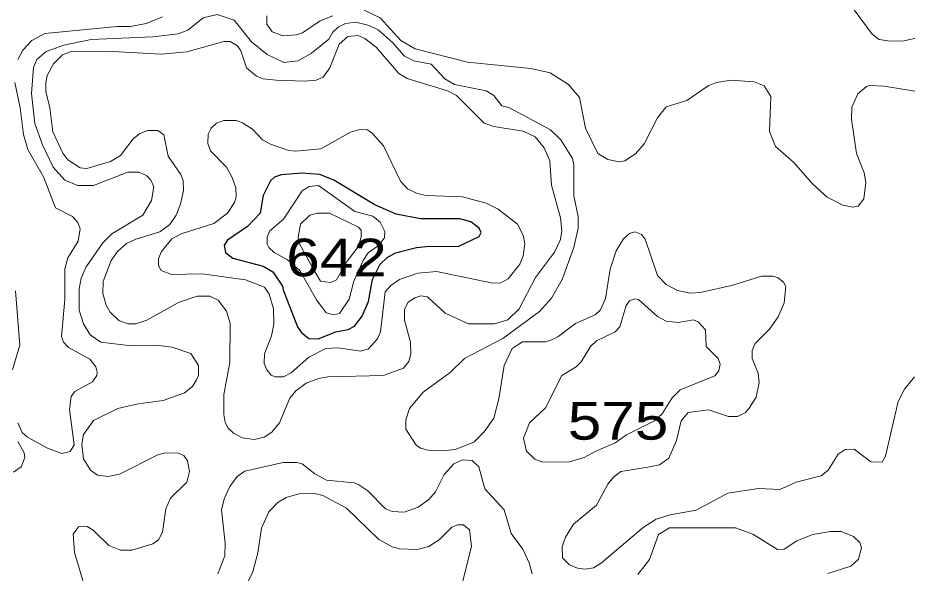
# Model space of a CAD drawing. Extents: x 577 to 602.9, y 7483.8 to 7511.6.
# Drawn here: x 582.841 to 584.735, y 7491.618 to 7492.8 of the extents above; entities that cross this region are included whole.
import ezdxf
from ezdxf.enums import TextEntityAlignment as Align

# ---------------------------------------------------------------- set-up
doc = ezdxf.new("R2010")
doc.units = 0
doc.header["$LTSCALE"] = 0.032
doc.layers.add('1', color=7, linetype='Continuous', lineweight=25)
doc.layers.add('2', color=7, linetype='Continuous', lineweight=13)
doc.layers.add('61', color=7, linetype='Continuous')

msp = doc.modelspace()

# ---------------------------------------------------------------- linework, layer by layer
at = {"layer": '1'}
msp.add_lwpolyline([(583.4063, 7492.2213), (583.4364, 7492.1426), (583.4452, 7492.1307), (583.4611, 7492.118), (583.4809, 7492.1172), (583.5183, 7492.1323), (583.5446, 7492.1371), (583.5581, 7492.1442), (583.5748, 7492.1657), (583.5883, 7492.1967), (583.5962, 7492.2436), (583.6129, 7492.2762), (583.628, 7492.2905), (583.6455, 7492.3001), (583.6901, 7492.3112), (583.7179, 7492.3144), (583.7791, 7492.3136), (583.8237, 7492.3351), (583.8276, 7492.3438), (583.8237, 7492.3526), (583.8062, 7492.3661), (583.7823, 7492.3724), (583.6988, 7492.3724), (583.6471, 7492.3828), (583.6018, 7492.4027), (583.5143, 7492.4551), (583.4841, 7492.4671), (583.446, 7492.4695), (583.4022, 7492.4663), (583.3879, 7492.4615), (583.3792, 7492.4536), (583.3633, 7492.4225), (583.3569, 7492.3844), (583.3299, 7492.3565), (583.2877, 7492.3271), (583.2806, 7492.3168), (583.2837, 7492.3009), (583.2988, 7492.289), (583.3633, 7492.2715), (583.3839, 7492.2595), (583.4046, 7492.2293)], close=True, dxfattribs=at)
at = {"layer": '2'}
for points in [[(583.1494, 7492.8026), (583.1144, 7492.7883), (583.081, 7492.782), (583.0531, 7492.782), (582.8989, 7492.7669), (582.871, 7492.7525), (582.852, 7492.7319), (582.8408, 7492.712)], [(584.2038, 7492.2516), (584.1775, 7492.3295), (584.1696, 7492.339), (584.1552, 7492.3446), (584.1441, 7492.3414), (584.1314, 7492.3303), (584.1155, 7492.3041), (584.1028, 7492.2651), (584.0924, 7492.2031), (584.0821, 7492.1792), (584.071, 7492.1681), (584.0288, 7492.1498), (583.9914, 7492.1212), (583.9763, 7492.114), (583.9652, 7492.1108), (583.9159, 7492.1108), (583.8936, 7492.0965), (583.8769, 7492.0607), (583.8658, 7491.9892), (583.8547, 7491.9486), (583.834, 7491.9192), (583.8125, 7491.8969), (583.7728, 7491.8818), (583.7449, 7491.8786), (583.7147, 7491.8802), (583.6988, 7491.8842), (583.6893, 7491.8906), (583.6678, 7491.9248), (583.6678, 7491.9446), (583.675, 7491.9685), (583.7044, 7492.0035), (583.7616, 7492.0456), (583.7926, 7492.075), (583.8738, 7492.118), (583.9525, 7492.1752), (583.9779, 7492.2039), (584.0002, 7492.2436), (584.0256, 7492.3112), (584.0344, 7492.3526), (584.0344, 7492.3772), (584.0256, 7492.4217), (584.0256, 7492.487), (584.0225, 7492.5013), (583.9978, 7492.541), (583.9755, 7492.5617), (583.8865, 7492.6094), (583.8722, 7492.6134), (583.8547, 7492.6349), (583.8388, 7492.6452), (583.7712, 7492.6587), (583.7505, 7492.6706), (583.7211, 7492.7016), (583.6845, 7492.7088), (583.6646, 7492.7191), (583.6392, 7492.7478), (583.6082, 7492.7748), (583.5891, 7492.7843), (583.5613, 7492.7915), (583.539, 7492.7883), (583.5239, 7492.7812), (583.512, 7492.77), (583.5032, 7492.7549), (583.4666, 7492.7255), (583.438, 7492.7088), (583.4078, 7492.7056), (583.372, 7492.7223), (583.3386, 7492.7494), (583.302, 7492.7955), (583.2654, 7492.8074), (583.236, 7492.8003), (583.2034, 7492.774), (583.1827, 7492.7661), (583.1287, 7492.7597), (582.9975, 7492.7541), (582.9394, 7492.7422), (582.9013, 7492.7287), (582.8814, 7492.712), (582.8742, 7492.6945), (582.8702, 7492.6396), (582.8774, 7492.5752), (582.8933, 7492.5299), (582.9164, 7492.4822), (582.941, 7492.4551), (582.9688, 7492.4432), (583.0022, 7492.4432), (583.0754, 7492.4718), (583.0993, 7492.4718), (583.116, 7492.4639), (583.1247, 7492.4551), (583.1311, 7492.4408), (583.1255, 7492.4114), (583.1072, 7492.3804), (583.0412, 7492.3406), (583.0221, 7492.3216), (582.9863, 7492.2707), (582.976, 7492.246), (582.972, 7492.2237), (582.972, 7492.1784), (582.9808, 7492.149), (582.9951, 7492.1259), (583.0181, 7492.11)], [(583.512, 7492.805), (583.4849, 7492.7939), (583.4475, 7492.7684), (583.4348, 7492.7645), (583.4054, 7492.7621), (583.3831, 7492.7708), (583.3712, 7492.7867)], [(583.3712, 7492.7867), (583.3712, 7492.805)], [(584.7779, 7492.6404), (584.6864, 7492.6547), (584.6546, 7492.6563), (584.6483, 7492.6539), (584.63, 7492.6388), (584.6172, 7492.6102), (584.6165, 7492.5848), (584.6276, 7492.5116), (584.6435, 7492.4703), (584.6475, 7492.4496), (584.6427, 7492.4154), (584.6308, 7492.3995), (584.6196, 7492.3971), (584.5982, 7492.4019), (584.5648, 7492.4186), (584.5345, 7492.4464), (584.4932, 7492.4933), (584.455, 7492.5267), (584.4423, 7492.5585), (584.4447, 7492.6333), (584.4304, 7492.6555), (584.4097, 7492.6643), (584.3604, 7492.6675), (584.3294, 7492.6627), (584.3111, 7492.6555), (584.2658, 7492.6245), (584.222, 7492.611), (584.2038, 7492.5879), (584.1751, 7492.5323), (584.1568, 7492.5108), (584.1338, 7492.4957), (584.1219, 7492.4941), (584.098, 7492.4989), (584.0765, 7492.5116), (584.0503, 7492.5657), (584.0376, 7492.6309), (584.0137, 7492.6587), (583.9747, 7492.6834), (583.9334, 7492.6929), (583.799, 7492.7064), (583.6877, 7492.7343), (583.6567, 7492.7525), (583.6129, 7492.8003), (583.5787, 7492.8169)], [(584.622, 7492.8177), (584.661, 7492.7653), (584.6753, 7492.7541), (584.6992, 7492.7509), (584.7278, 7492.7517), (584.7826, 7492.7637), (584.8677, 7492.8018)], [(582.9545, 7492.7287), (583.0309, 7492.7295), (583.1462, 7492.7231), (583.201, 7492.7279), (583.2798, 7492.7502), (583.2933, 7492.7502), (583.3092, 7492.7406), (583.3163, 7492.7303), (583.3283, 7492.6937), (583.3497, 7492.6762), (583.3633, 7492.6706), (583.3911, 7492.6675), (583.4523, 7492.6659), (583.4762, 7492.6675), (583.4913, 7492.6738), (583.5056, 7492.6937), (583.5255, 7492.7446), (583.5438, 7492.7605), (583.566, 7492.7629), (583.5803, 7492.7565), (583.6042, 7492.7382), (583.6519, 7492.6826), (583.6702, 7492.6714), (583.7561, 7492.6452), (583.7752, 7492.6349), (583.834, 7492.576), (583.8547, 7492.5689), (583.9175, 7492.5593), (583.9429, 7492.5474), (583.962, 7492.5235), (583.9739, 7492.4957), (583.9779, 7492.444), (583.997, 7492.3748), (583.9994, 7492.347), (583.997, 7492.3287), (583.9843, 7492.3017), (583.9437, 7492.2476), (583.9087, 7492.1808), (583.8849, 7492.1577), (583.8563, 7492.149), (583.8006, 7492.149), (583.7513, 7492.1721), (583.7139, 7492.2063), (583.6996, 7492.2086), (583.6869, 7492.2047), (583.6726, 7492.1951), (583.6646, 7492.18), (583.6646, 7492.157), (583.6773, 7492.11), (583.6781, 7492.0846), (583.6742, 7492.0687), (583.6622, 7492.0544), (583.6201, 7492.0393), (583.5016, 7492.0361), (583.4825, 7492.0329), (583.4555, 7492.0226), (583.4332, 7492.0067), (583.4205, 7491.9908), (583.3982, 7491.9383), (583.3823, 7491.9184), (583.3656, 7491.9081), (583.3442, 7491.9025), (583.3187, 7491.9065), (583.3004, 7491.916), (583.2893, 7491.9271), (583.2829, 7491.9391), (583.2798, 7491.9558), (583.2798, 7491.9987), (583.2925, 7492.0671), (583.2933, 7492.1498), (583.2853, 7492.176), (583.2678, 7492.1991), (583.2503, 7492.2078), (583.2233, 7492.2078), (583.1835, 7492.1943), (583.116, 7492.157), (583.0921, 7492.149), (583.0754, 7492.149), (583.0563, 7492.1562), (583.038, 7492.1737), (583.0293, 7492.1888), (583.0221, 7492.2134), (583.0229, 7492.2389), (583.0396, 7492.2842), (583.0531, 7492.3033), (583.0722, 7492.32), (583.0921, 7492.3295), (583.1438, 7492.3446), (583.1645, 7492.3605), (583.178, 7492.3804), (583.1875, 7492.4035), (583.1939, 7492.4329), (583.1931, 7492.4543), (583.1883, 7492.4671), (583.1613, 7492.506), (583.1517, 7492.5514), (583.139, 7492.5609), (583.1175, 7492.5609), (583.1001, 7492.5537), (583.0865, 7492.5426), (583.0595, 7492.5076)], [(583.0595, 7492.5076), (583.0388, 7492.4949), (582.9879, 7492.4798), (582.9736, 7492.4814), (582.9474, 7492.4981), (582.937, 7492.5124), (582.9156, 7492.5577), (582.9092, 7492.6086), (582.9005, 7492.6436), (582.9005, 7492.6619), (582.9036, 7492.6778), (582.9172, 7492.7024), (582.9362, 7492.7215), (582.9545, 7492.7287)], [(582.8345, 7492.6627), (582.8464, 7492.6086), (582.8535, 7492.5522), (582.8623, 7492.5203), (582.8957, 7492.4623), (582.9211, 7492.3963), (582.9577, 7492.3772), (582.9688, 7492.3645), (582.9736, 7492.351), (582.9696, 7492.3247), (582.9474, 7492.2897), (582.941, 7492.2659), (582.941, 7492.2007), (582.9339, 7492.122), (582.9386, 7492.11), (582.949, 7492.0989), (582.9943, 7492.0735), (583.007, 7492.0576), (583.0102, 7492.0464), (583.0094, 7492.0393), (582.9999, 7492.0257), (582.9625, 7492.0051), (582.9545, 7491.9947), (582.9514, 7491.9669), (582.9609, 7491.8914), (582.9529, 7491.8771), (582.9347, 7491.8731), (582.9044, 7491.8842), (582.8615, 7491.9081), (582.8504, 7491.9176), (582.8408, 7491.9383)], [(584.7508, 7492.0361), (584.7294, 7492.0098), (584.7158, 7491.9836), (584.6888, 7491.8675), (584.6817, 7491.8548), (584.6578, 7491.8556), (584.622, 7491.8826), (584.6029, 7491.8818), (584.5886, 7491.8715), (584.5672, 7491.8373), (584.552, 7491.8254), (584.4988, 7491.8118), (584.4638, 7491.7967), (584.4185, 7491.7983), (584.3532, 7491.7888), (584.2857, 7491.7522), (584.2308, 7491.7427), (584.2006, 7491.7331), (584.1727, 7491.7156), (584.0845, 7491.6401), (584.067, 7491.6298), (584.0495, 7491.6266), (584.0328, 7491.629), (584.0161, 7491.6361), (584.001, 7491.6512), (584.0002, 7491.6743), (584.0073, 7491.695), (584.0248, 7491.7228), (584.0733, 7491.7633), (584.0977, 7491.8079), (584.1096, 7491.823), (584.1251, 7491.8346), (584.1828, 7491.8439), (584.2075, 7491.849), (584.2276, 7491.863), (584.2443, 7491.9009), (584.2539, 7491.9423), (584.269, 7491.9605), (584.3119, 7491.9661), (584.3548, 7491.9518), (584.3739, 7491.9518), (584.3906, 7491.9605), (584.3986, 7491.9693), (584.4137, 7491.9931), (584.42, 7492.0242), (584.4177, 7492.044), (584.4049, 7492.075), (584.4049, 7492.0925), (584.4113, 7492.1069), (584.4423, 7492.1379), (584.4606, 7492.1641), (584.4733, 7492.1935), (584.4765, 7492.2277), (584.4725, 7492.2373), (584.4606, 7492.2468), (584.4495, 7492.2508), (584.4248, 7492.2508), (584.3636, 7492.2317), (584.2952, 7492.2158), (584.2729, 7492.2142), (584.2459, 7492.2198), (584.222, 7492.2325), (584.2038, 7492.2516)], [(582.8297, 7492.0512), (582.8456, 7492.1037), (582.8361, 7492.219)], [(583.0181, 7492.11), (583.077, 7492.1029), (583.1358, 7492.1037), (583.17, 7492.0997), (583.2098, 7492.0862), (583.2257, 7492.0607), (583.2257, 7492.0393), (583.2217, 7492.0297), (583.213, 7492.0154), (583.1963, 7492.0019), (583.1509, 7491.986), (583.0977, 7491.9788), (583.0539, 7491.9685), (583.0022, 7491.9431), (582.9808, 7491.9136), (582.9776, 7491.893), (582.9808, 7491.8619), (582.9959, 7491.8373), (583.011, 7491.827), (583.0333, 7491.8238), (583.0579, 7491.8293), (583.139, 7491.8699), (583.1557, 7491.8747), (583.1835, 7491.8739), (583.1947, 7491.8691), (583.2026, 7491.8572), (583.2066, 7491.8349), (583.201, 7491.8118), (583.1661, 7491.7777), (583.1565, 7491.7554), (583.1494, 7491.7053), (583.1406, 7491.6894), (583.1287, 7491.6806), (583.0841, 7491.6671), (583.0595, 7491.6671), (583.0348, 7491.6775), (583.0014, 7491.7101), (582.9887, 7491.718), (582.9704, 7491.7172), (582.9593, 7491.7013), (582.9617, 7491.6624), (582.984, 7491.5884)], [(582.8321, 7491.8333), (582.848, 7491.8444), (582.8559, 7491.8643), (582.8543, 7491.8747), (582.8408, 7491.8985)], [(583.267, 7491.617), (583.2821, 7491.6552), (583.2829, 7491.6822), (583.275, 7491.753), (583.2806, 7491.7769), (583.2925, 7491.8031), (583.3084, 7491.8238), (583.3243, 7491.8357), (583.4062, 7491.854), (583.4356, 7491.854), (583.4467, 7491.8508), (583.4738, 7491.8301), (583.4984, 7491.8166), (583.5573, 7491.8103), (583.5676, 7491.8063), (583.5867, 7491.7936), (583.6241, 7491.7554), (583.6384, 7491.7498), (583.6638, 7491.7482), (583.694, 7491.7586), (583.7163, 7491.7753), (583.7306, 7491.7912), (583.7489, 7491.8285), (583.7696, 7491.8508), (583.7879, 7491.8596), (583.8086, 7491.858), (583.8229, 7491.8444), (583.8356, 7491.7975), (583.8769, 7491.753), (583.892, 7491.7029), (583.9167, 7491.6695), (583.9302, 7491.6401), (583.9366, 7491.617)], [(583.7871, 7491.5964), (583.807, 7491.6751), (583.803, 7491.7109), (583.7903, 7491.7212), (583.7783, 7491.7212), (583.7656, 7491.7164), (583.7394, 7491.6902), (583.7163, 7491.6751), (583.6917, 7491.6687), (583.6543, 7491.6703), (583.6384, 7491.6743), (583.6098, 7491.6902), (583.5414, 7491.757), (583.4905, 7491.784), (583.473, 7491.788), (583.4396, 7491.7872), (583.4126, 7491.7792), (583.3959, 7491.7697), (583.376, 7491.749), (583.3601, 7491.714), (583.3521, 7491.6616), (583.3418, 7491.621), (583.3267, 7491.5908)], [(584.1616, 7491.6154), (584.1863, 7491.6472), (584.2053, 7491.7005), (584.2292, 7491.7148), (584.3699, 7491.7148), (584.4065, 7491.7013), (584.459, 7491.6687), (584.4733, 7491.6695), (584.5004, 7491.687), (584.5345, 7491.7005), (584.5719, 7491.7069), (584.595, 7491.7069), (584.6212, 7491.6965), (584.6347, 7491.6838), (584.6379, 7491.6719), (584.6316, 7491.648), (584.6149, 7491.6329), (584.5664, 7491.6178)]]:
    msp.add_lwpolyline(points, dxfattribs=at)
for points in [[(583.3815, 7492.1236), (583.3664, 7492.0854), (583.3656, 7492.0647), (583.3712, 7492.0512), (583.3807, 7492.0401), (583.3895, 7492.0361), (583.407, 7492.0361), (583.4229, 7492.0448), (583.4611, 7492.0782), (583.4968, 7492.0965), (583.5223, 7492.0981), (583.5716, 7492.091), (583.5883, 7492.0957), (583.6074, 7492.1172), (583.6137, 7492.1323), (583.6233, 7492.2174), (583.6352, 7492.2309), (583.6543, 7492.2436), (583.6933, 7492.2571), (583.733, 7492.2603), (583.8531, 7492.2357), (583.8698, 7492.2365), (583.8857, 7492.2452), (583.9103, 7492.2762), (583.9175, 7492.2937), (583.9207, 7492.3192), (583.9175, 7492.3375), (583.9056, 7492.3613), (583.8642, 7492.3931), (583.8388, 7492.4058), (583.7879, 7492.4194), (583.7107, 7492.4225), (583.6917, 7492.4265), (583.671, 7492.4361), (583.6559, 7492.4528), (583.6201, 7492.5283), (583.5954, 7492.5553), (583.5851, 7492.5617), (583.5692, 7492.5625), (583.5493, 7492.5569), (583.4865, 7492.5219), (583.4332, 7492.5164), (583.4181, 7492.518), (583.3792, 7492.5315), (583.3625, 7492.541), (583.341, 7492.5633), (583.3195, 7492.5768), (583.306, 7492.5816), (583.2798, 7492.5816), (583.2639, 7492.576), (583.2527, 7492.5657), (583.2464, 7492.553), (583.2456, 7492.5331), (583.2511, 7492.5172), (583.2853, 7492.4822), (583.2973, 7492.4607), (583.3052, 7492.4384), (583.306, 7492.4194), (583.3028, 7492.4074), (583.2877, 7492.3844), (583.2583, 7492.3629), (583.1891, 7492.3406), (583.1692, 7492.3303), (583.147, 7492.3033), (583.1406, 7492.2882), (583.1406, 7492.273), (583.1462, 7492.2627), (583.1684, 7492.254), (583.2336, 7492.2556), (583.3259, 7492.2428), (583.3664, 7492.2269), (583.3762, 7492.2125), (583.3857, 7492.1813), (583.3865, 7492.1486)], [(583.4157, 7492.285), (583.3871, 7492.3009), (583.376, 7492.3112), (583.372, 7492.3184), (583.372, 7492.3343), (583.3776, 7492.347), (583.407, 7492.3717), (583.4467, 7492.4321), (583.4619, 7492.4416), (583.4817, 7492.4432), (583.5589, 7492.3883), (583.597, 7492.378), (583.6129, 7492.3653), (583.6225, 7492.3454), (583.6217, 7492.3319), (583.6082, 7492.3152), (583.5875, 7492.3001), (583.5764, 7492.2842), (583.5565, 7492.2397), (583.5469, 7492.2015), (583.5263, 7492.1713), (583.5135, 7492.1681), (583.4975, 7492.1728), (583.4772, 7492.2003), (583.4414, 7492.2624)], [(583.469, 7492.2691), (583.442, 7492.3176), (583.438, 7492.3335), (583.4428, 7492.3613), (583.4627, 7492.3804), (583.4794, 7492.3844), (583.5048, 7492.3844), (583.5668, 7492.355), (583.5724, 7492.3486), (583.5724, 7492.3335), (583.566, 7492.3128), (583.5422, 7492.2826), (583.5199, 7492.2428), (583.5072, 7492.2373), (583.4857, 7492.2397)], [(584.071, 7491.8771), (584.0471, 7491.8643), (584.0161, 7491.8556), (583.9596, 7491.8548), (583.9421, 7491.8611), (583.9246, 7491.8778), (583.9183, 7491.9057), (583.931, 7491.9383), (583.9652, 7491.9701), (583.9994, 7492.0393), (584.0304, 7492.0576), (584.0407, 7492.0679), (584.0606, 7492.1005), (584.0733, 7492.1132), (584.1131, 7492.1323), (584.1234, 7492.1426), (584.137, 7492.188), (584.1441, 7492.1983), (584.1552, 7492.2023), (584.1632, 7492.2007), (584.2038, 7492.1649), (584.222, 7492.1546), (584.2475, 7492.1522), (584.2801, 7492.1577), (584.2904, 7492.153), (584.3055, 7492.1363), (584.3071, 7492.1005), (584.3326, 7492.075), (584.3373, 7492.0631), (584.3342, 7492.0488), (584.3254, 7492.0385), (584.2515, 7492.0083), (584.2348, 7491.9916), (584.2133, 7491.9574), (584.1974, 7491.9423), (584.1378, 7491.9128), (584.1131, 7491.8961)]]:
    msp.add_lwpolyline(points, close=True, dxfattribs=at)

# ---------------------------------------------------------------- texts
at = {"layer": '61', "width": 1.2}
for s, p in [('642', (583.5199, 7492.2503)), ('575', (584.1195, 7491.9025))]:
    msp.add_text(s, height=0.08, dxfattribs=at).set_placement(p, align=Align.CENTER)

doc.saveas('drawing.dxf')
